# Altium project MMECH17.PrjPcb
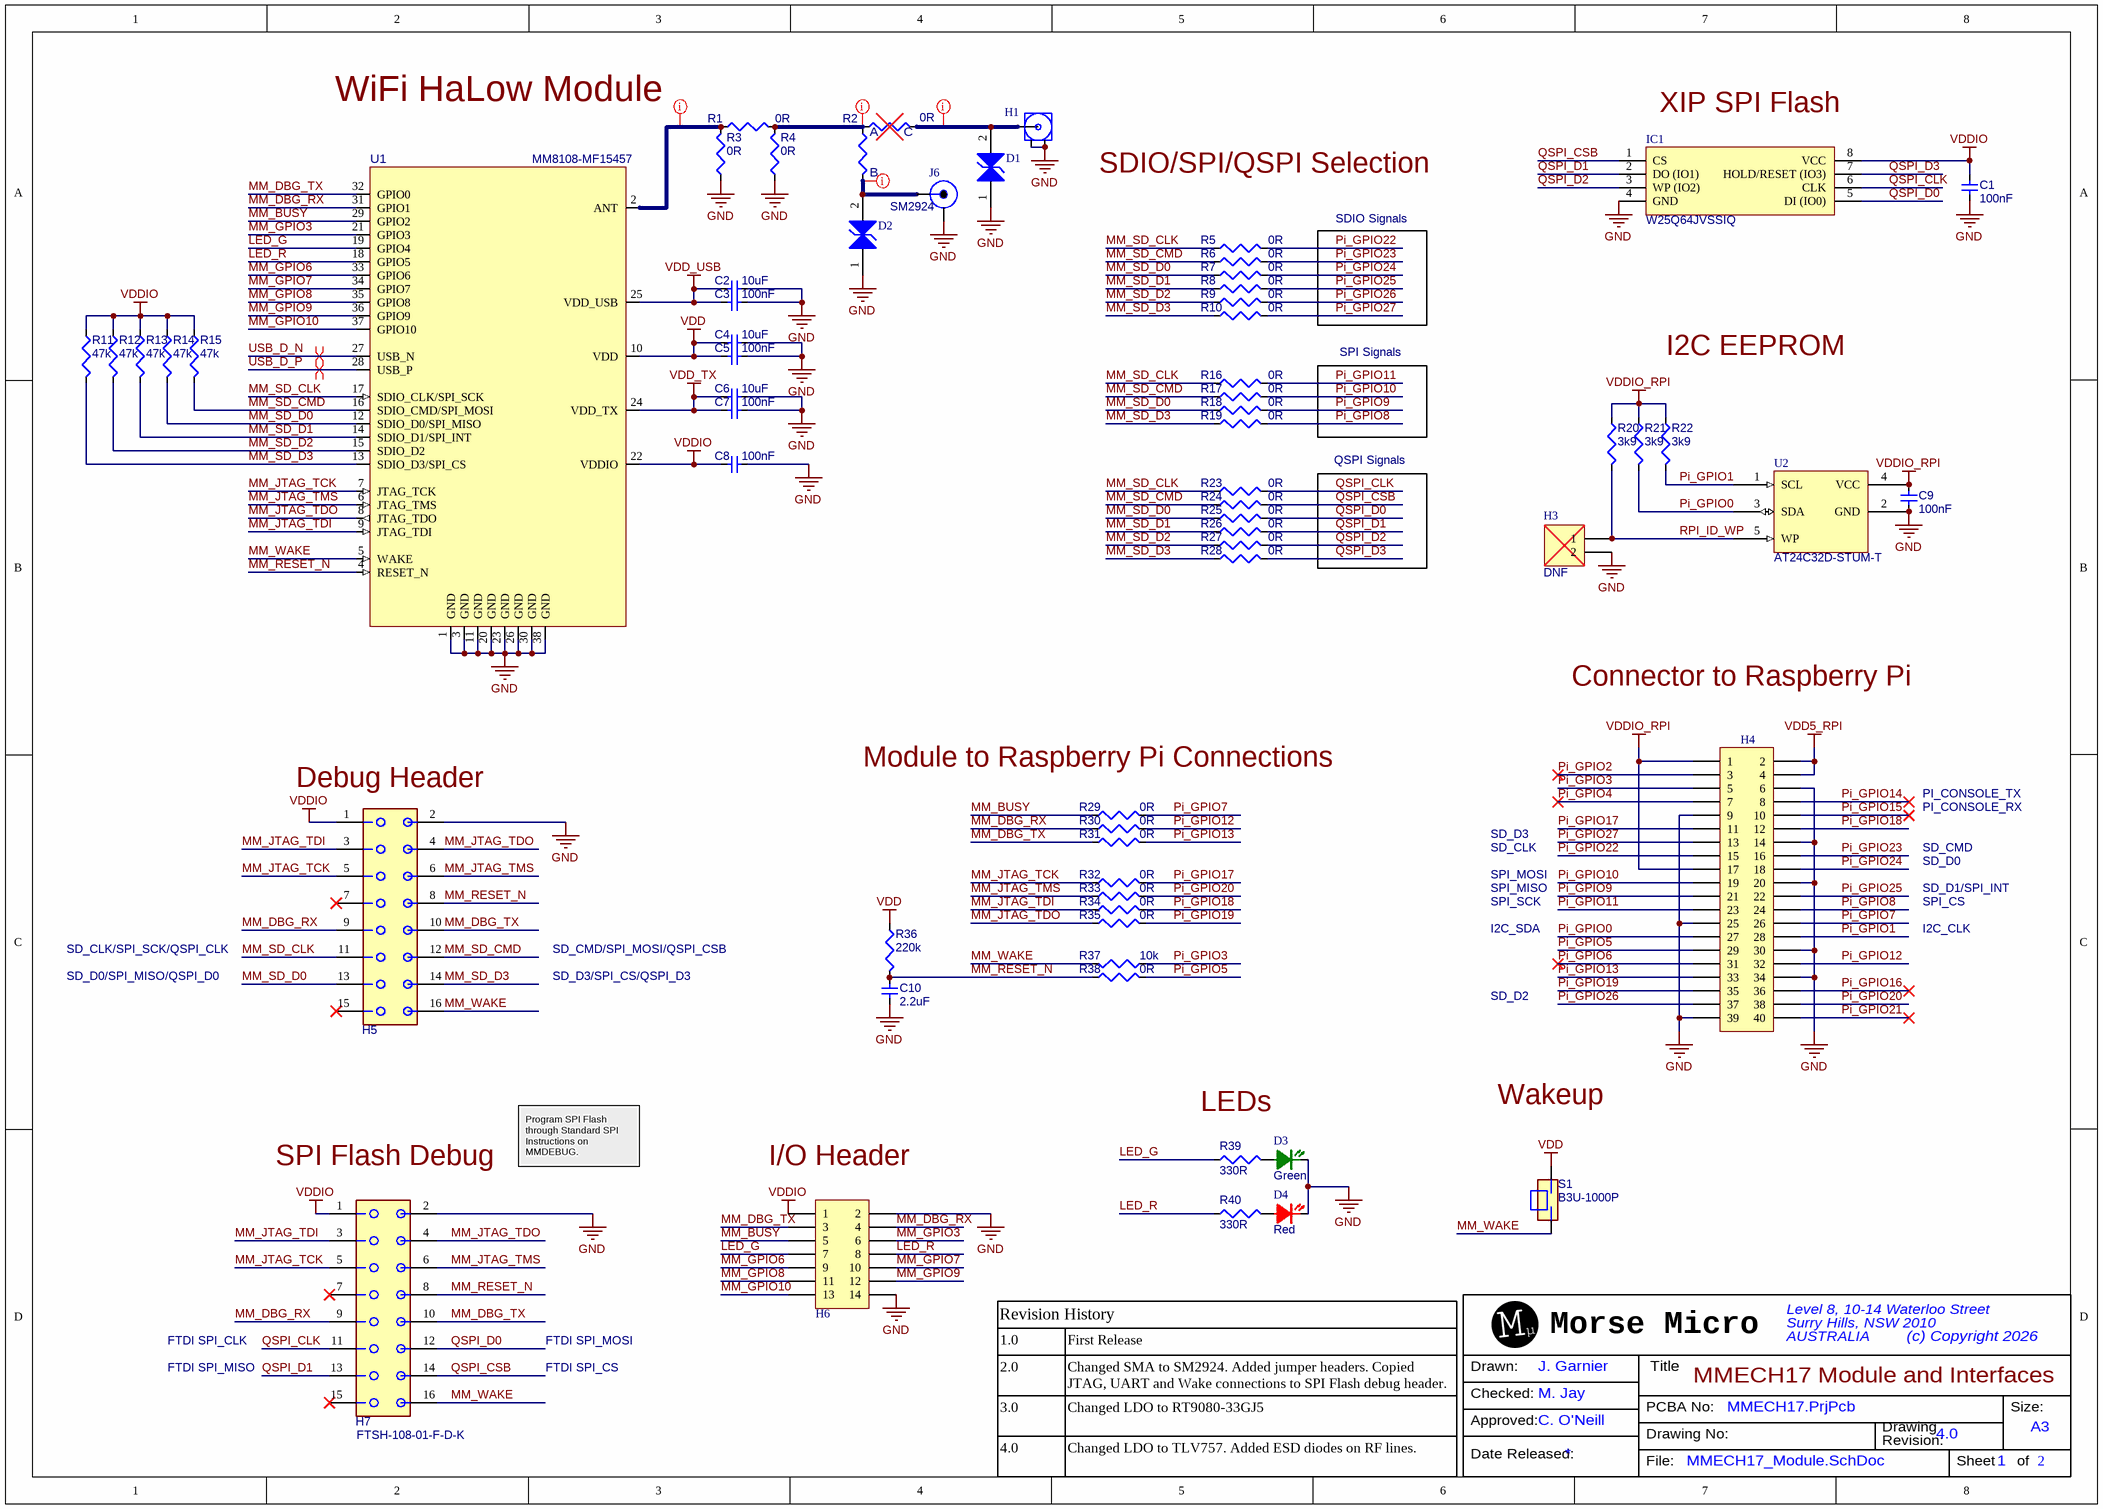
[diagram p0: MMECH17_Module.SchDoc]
ApprovedBy: C. O'Neill; CheckedBy: M. Jay; DrawnBy: J. Garnier; Project: MMECH17; Revision: 4.0
2 sheets, 96 parts. Net scope: global (net labels, ports and power ports of the same name join across sheets).
Board file: MMECH17.PcbDoc
Sheets:
  MMECH17_Module.SchDoc
  MMECH17_Power.SchDoc

## Sheet MMECH17_Module.SchDoc: MMECH17 Module and Interfaces
size A3; SheetNumber: 1; SheetTotal: 2; PageSetup: Record=PageOptions¦CenterHorizontal=True¦CenterVertical=True¦PrintScale=1.04¦XCorrection=1.00¦YCorrection=1.00¦PrintKind=0¦BorderSize=5000000¦LeftOffset=0¦BottomOffset=0¦Orientation=2¦PaperLength=1000¦PaperWidth=1000¦Scale=100¦PaperSource=7¦PrintQuality=-4¦MediaType=1¦DitherType=10¦PaperKind=A3¦PrintScaleMode=1

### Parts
C1  value 100nF  [0402_cap]  (hidden comment: C0402C104K8RACTU)
C2  value 10uF  [0603_cap]  (hidden comment: GRM188R61E106MA73J)
C3  value 100nF  [0402_cap]  (hidden comment: C0402C104K8RACTU)
C4  value 10uF  [0603_cap]  (hidden comment: GRM188R61E106MA73J)
C5  value 100nF  [0402_cap]  (hidden comment: C0402C104K8RACTU)
C6  value 10uF  [0603_cap]  (hidden comment: GRM188R61E106MA73J)
C7  value 100nF  [0402_cap]  (hidden comment: C0402C104K8RACTU)
C8  value 100nF  [0402_cap]  (hidden comment: C0402C104K8RACTU)
C9  value 100nF  [0402_cap]  (hidden comment: C0402C104K8RACTU)
C10  value 2.2uF  [0402_cap]  (hidden comment: JMK105BJ225MV-F)
D1  ESD103B102ELE6327XTMA1  [INF-TSLP-2-20_V]  (value not drawn)
D2  ESD103B102ELE6327XTMA1  [INF-TSLP-2-20_V]  (value not drawn)
D3  value Green  [LED_0402_GREEN]  (hidden comment: XZVGR68W-3)
D4  value Red  [LED_0402_RED]  (hidden comment: XZMDK68W-2)
H1  U.FL-R-SMT  [U_FL-R-SMT]  (value not drawn)
H3  DNF  [HDR1X2_DNF]  (no BOM)
H4  PPPC202LFBN-RC  [HDR2X20F]  (value not drawn)
H5  FTSH-108-01-F-D-K  [FTSH_108_D_K]  (value not drawn)
H6  PBC07DFAN  [HDR2X7]  (value not drawn)
H7  FTSH-108-01-F-D-K  [FTSH_108_D_K]
IC1  W25Q64JVSSIQ  [SOIC127P790X216-8N]
J6  SM2924  [SM2924]
R1  value 0R  [0603_res_rnd]  (hidden comment: RC0603JR-070RL)
R2  value 0R  [0603_res_ab_ra]  (hidden comment: RC0603JR-070RL)
R3  value 0R  [0603_res_rnd]  (hidden comment: RC0603JR-070RL)
R4  value 0R  [0603_res_rnd]  (hidden comment: RC0603JR-070RL)
R5  value 0R  [0603_res]  (hidden comment: ERJ-3GEY0R00V)
R6  value 0R  [0603_res]  (hidden comment: ERJ-3GEY0R00V)
R7  value 0R  [0603_res]  (hidden comment: ERJ-3GEY0R00V)
R8  value 0R  [0603_res]  (hidden comment: ERJ-3GEY0R00V)
R9  value 0R  [0603_res]  (hidden comment: ERJ-3GEY0R00V)
R10  value 0R  [0603_res]  (hidden comment: ERJ-3GEY0R00V)
R11  value 47k  [0402_res]  (hidden comment: MCR01MZPF4702)
R12  value 47k  [0402_res]  (hidden comment: MCR01MZPF4702)
R13  value 47k  [0402_res]  (hidden comment: MCR01MZPF4702)
R14  value 47k  [0402_res]  (hidden comment: MCR01MZPF4702)
R15  value 47k  [0402_res]  (hidden comment: MCR01MZPF4702)
R16  value 0R  [0603_res]  (hidden comment: ERJ-3GEY0R00V)
R17  value 0R  [0603_res]  (hidden comment: ERJ-3GEY0R00V)
R18  value 0R  [0603_res]  (hidden comment: ERJ-3GEY0R00V)
R19  value 0R  [0603_res]  (hidden comment: ERJ-3GEY0R00V)
R20  value 3k9  [0402_res]  (hidden comment: RC0402FR-073K9L)
R21  value 3k9  [0402_res]  (hidden comment: RC0402FR-073K9L)
R22  value 3k9  [0402_res]  (hidden comment: RC0402FR-073K9L)
R23  value 0R  [0603_res]  (hidden comment: ERJ-3GEY0R00V)
R24  value 0R  [0603_res]  (hidden comment: ERJ-3GEY0R00V)
R25  value 0R  [0603_res]  (hidden comment: ERJ-3GEY0R00V)
R26  value 0R  [0603_res]  (hidden comment: ERJ-3GEY0R00V)
R27  value 0R  [0603_res]  (hidden comment: ERJ-3GEY0R00V)
R28  value 0R  [0603_res]  (hidden comment: ERJ-3GEY0R00V)
R29  value 0R  [0603_res]  (hidden comment: ERJ-3GEY0R00V)
R30  value 0R  [0603_res]  (hidden comment: ERJ-3GEY0R00V)
R31  value 0R  [0603_res]  (hidden comment: ERJ-3GEY0R00V)
R32  value 0R  [0603_res]  (hidden comment: ERJ-3GEY0R00V)
R33  value 0R  [0603_res]  (hidden comment: ERJ-3GEY0R00V)
R34  value 0R  [0603_res]  (hidden comment: ERJ-3GEY0R00V)
R35  value 0R  [0603_res]  (hidden comment: ERJ-3GEY0R00V)
R36  value 220k  [0402_res]  (hidden comment: RC0402FR-07220KL)
R37  value 10k  [0603_res]  (hidden comment: RG1608P-103-B-T5)
R38  value 0R  [0603_res]  (hidden comment: ERJ-3GEY0R00V)
R39  value 330R  [0402_res]  (hidden comment: RC0402FR-07330RL)
R40  value 330R  [0402_res]  (hidden comment: RC0402FR-07330RL)
S1  B3U-1000P  [B3U-1000P]
U1  value MM8108-MF15457  [MF15]  (hidden comment: MM8108-MF15)
U2  AT24C32D-STUM-T  [SOT-23_5]

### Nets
GND: C1.1 C2.2 C3.2 C4.2 C5.1 C6.2 C7.2 C8.2 C9.1 C10.2 D1.1(C) D2.1(C) D3.K D4.K H1.2 H1.3 H3.2 H4.6 H4.9 H4.14 H4.20 H4.25 H4.30 H4.34 H4.39 H5.2 H6.2 H6.14 H7.2 IC1.4(GND) J6.2 R3.1 R4.1 U1.1(GND) U1.3(GND) U1.11(GND) U1.20(GND) U1.23(GND) U1.26(GND) U1.30(GND) U1.38(GND) U2.2(GND)
VDD: C4.1 C5.2 R36.1 S1.2 U1.10(VDD)
VDD5_RPI: H4.2 H4.4
VDD_TX: C6.1 C7.1 U1.24(VDD_TX)
VDD_USB: C2.1 C3.1 U1.25(VDD_USB)
VDDIO: C1.2 C8.1 H5.1 H6.1 H7.1 IC1.8(VCC) R11.1 R12.1 R13.1 R14.1 R15.1 U1.22(VDDIO)
VDDIO_RPI: C9.2 H4.1 H4.17 R20.1 R21.1 R22.1 U2.4(VCC)
LED_G: H6.7 R39.1 U1.19(GPIO4)
LED_R: H6.8 R40.1 U1.18(GPIO5)
MM_BUSY: H6.5 R29.1 U1.29(GPIO2)
MM_DBG_RX: H5.9 H6.4 H7.9 R30.1 U1.31(GPIO1)
MM_DBG_TX: H5.10 H6.3 H7.10 R31.1 U1.32(GPIO0)
MM_GPIO3: H6.6 U1.21(GPIO3)
MM_GPIO6: H6.9 U1.33(GPIO6)
MM_GPIO7: H6.10 U1.34(GPIO7)
MM_GPIO8: H6.11 U1.35(GPIO8)
MM_GPIO9: H6.12 U1.36(GPIO9)
MM_GPIO10: H6.13 U1.37(GPIO10)
MM_JTAG_TCK: H5.5 H7.5 R32.1 U1.7(JTAG_TCK)
MM_JTAG_TDI: H5.3 H7.3 R34.1 U1.9(JTAG_TDI)
MM_JTAG_TDO: H5.4 H7.4 R35.1 U1.8(JTAG_TDO)
MM_JTAG_TMS: H5.6 H7.6 R33.1 U1.6(JTAG_TMS)
MM_RESET_N: C10.1 H5.8 H7.8 R36.2 R38.1 U1.4(RESET_N)
MM_SD_CLK: H5.11 R5.1 R16.1 R23.1 U1.17(SDIO_CLK/SPI_SCK)
MM_SD_CMD: H5.12 R6.1 R15.2 R17.1 R24.1 U1.16(SDIO_CMD/SPI_MOSI)
MM_SD_D0: H5.13 R7.1 R14.2 R18.1 R25.1 U1.12(SDIO_D0/SPI_MISO)
MM_SD_D1: R8.1 R13.2 R26.1 U1.14(SDIO_D1/SPI_INT)
MM_SD_D2: R9.1 R12.2 R27.1 U1.15(SDIO_D2)
MM_SD_D3: H5.14 R10.1 R11.2 R19.1 R28.1 U1.13(SDIO_D3/SPI_CS)
MM_WAKE: H5.16 H7.16 R37.1 S1.1 U1.5(WAKE)
Pi_GPIO0: H4.27 R21.2 U2.3(SDA)
Pi_GPIO1: H4.28 R22.2 U2.1(SCL)
Pi_GPIO2: H4.3
Pi_GPIO3: H4.5 R37.2
Pi_GPIO4: H4.7
Pi_GPIO5: H4.29 R38.2
Pi_GPIO6: H4.31
Pi_GPIO7: H4.26 R29.2
Pi_GPIO8: H4.24 R19.2
Pi_GPIO9: H4.21 R18.2
Pi_GPIO10: H4.19 R17.2
Pi_GPIO11: H4.23 R16.2
Pi_GPIO12: H4.32 R30.2
Pi_GPIO13: H4.33 R31.2
Pi_GPIO14: H4.8
Pi_GPIO15: H4.10
Pi_GPIO16: H4.36
Pi_GPIO17: H4.11 R32.2
Pi_GPIO18: H4.12 R34.2
Pi_GPIO19: H4.35 R35.2
Pi_GPIO20: H4.38 R33.2
Pi_GPIO21: H4.40
Pi_GPIO22: H4.15 R5.2
Pi_GPIO23: H4.16 R6.2
Pi_GPIO24: H4.18 R7.2
Pi_GPIO25: H4.22 R8.2
Pi_GPIO26: H4.37 R9.2
Pi_GPIO27: H4.13 R10.2
QSPI_CLK: H7.11 IC1.6(CLK) R23.2
QSPI_CSB: H7.14 IC1.1(CS) R24.2
QSPI_D0: H7.12 IC1.5(DI_(IO0)) R25.2
QSPI_D1: H7.13 IC1.2(DO_(IO1)) R26.2
QSPI_D2: IC1.3(WP_(IO2)) R27.2
QSPI_D3: IC1.7(HOLD/RESET_(IO3)) R28.2
RPI_ID_WP: H3.1 R20.2 U2.5(WP)
USB_D_N: U1.27(USB_N)
USB_D_P: U1.28(USB_P)
NetD1_2: D1.2(C) H1.1 R2.C
NetD2_2: D2.2(C) J6.1 R2.B
NetD3_A: D3.A R39.2
NetD4_A: D4.A R40.2
NetR1_1: R1.1 R3.2 U1.2(ANT)
NetR1_2: R1.2 R2.A R4.2

Not connected (* = marked no-connect by the designer): H5 7* 15*; H7 7* 15*

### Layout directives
net class RF-Net: NetD1_2, NetD2_2, NetR1_1, NetR1_2
differential pair; differential pair class DIFF_90: USB_D_N, USB_D_P

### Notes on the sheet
- WiFi HaLow Module
- SDIO/SPI/QSPI Selection
- (near IC1) XIP SPI Flash
- SDIO Signals
- SPI Signals
- I2C EEPROM
- QSPI Signals
- Connector to Raspberry Pi
- Module to Raspberry Pi Connections
- (near H5) Debug Header
- SD_CLK
- SD_D3
- SD_CMD
- PI_CONSOLE_TX
- PI_CONSOLE_RX
- SPI_SCK
- SPI_MISO
- SPI_MOSI
- SD_D0
- SD_D1/SPI_INT
- SPI_CS
- SD_D0/SPI_MISO/QSPI_D0
- SD_CLK/SPI_SCK/QSPI_CLK
- SD_CMD/SPI_MOSI/QSPI_CSB
- SD_D3/SPI_CS/QSPI_D3
- I2C_SDA
- I2C_CLK
- SD_D2
- LEDs
- Wakeup
- (near H7) SPI Flash Debug
- Program SPI Flash through Standard SPI Instructions on MMDEBUG.
- (near H6) I/O Header
- Revision History
- FTDI SPI_CLK
- FTDI SPI_MISO
- FTDI SPI_CS
- FTDI SPI_MOSI
- 1.0
- 2.0
- First Release
- Changed SMA to SM2924. Added jumper headers. Copied JTAG, UART and Wake connections to SPI Flash debug header.
- 3.0
- Changed LDO to RT9080-33GJ5
- 4.0
- Changed LDO to TLV757. Added ESD diodes on RF lines.

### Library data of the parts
C1 C3 C7 C9 = CAP0025-15: CAP CER 100NF 10V ±10% X7R 0402; Subtype: Ceramic; Generic Allowed: Yes
C2 C4 C6 = CAP0197-10: CAP CER 10UF 25V ±20% X5R 0603; Generic Allowed: Yes; Subtype: Ceramic
C5 C8 = CAP0025-15: CAP CER 100NF 10V ±10% X7R 0402; Generic Allowed: Yes; Subtype: Ceramic
C10 = CAP0027-15: CAP CER 2.2UF 6.3V ±20% X5R 0402; Generic Allowed: Yes; Subtype: Ceramic
D1 D2 = DIO0089-8: ESD103B102 Series 1 Line 15 V 0.2pF Bi-Direction TVS Protection Device-TSLP-2-20
D3 = DIO0053-7: LED GREEN 0402 SMD; Generic Allowed: Yes; Voltage: 2.0V
D4 = DIO0052-9: LED RED 0402 SMD; Generic Allowed: Yes; Voltage: 1.95V
H1 = JCK0091-7: U.FL RF Connector; Generic Allowed: Yes
H3 = HDR0067-2: Conn Straight Header 2x1 0.100" 2 POS (DNF)
H4 = HDR0101-2: Conn Female Header 20x2 0.100" 40 POS; Generic Allowed: Yes
H5 H7 = HDR0110-2: Board Connector, 16 Contact(s), 2 Row(s), Male, Straight, 0.05 inch Pitch, Solder Terminal, Locking
H6 = HDR0095-2: Conn Straight Header 7x2 0.100" 14 POS; Generic Allowed: Yes
IC1 = ICT0225-3: Integrated Circuit; Manufacturer_Name: Winbond
J6 = JCK0138-23: Wanshih RF SMD SMA connector with 2 GND pillars - Smaller Connector Barrel
R1 R3 R4 = RES0119-8: RES SMD 0R OHM ±5% 1/10W 0603; Generic Allowed: Yes
R2 = RES0284-2: RES 0 OHM JUMPER 1/10W 0603; Subtype: Thick Film; Generic Allowed: Yes
R5-R10 R16-R19 R23-R35 R38 = RES0003-8: RES SMD 0R OHM ±1% 1/10W 0603; Generic Allowed: Yes
R11-R15 = RES0086-13: RES SMD 47K OHM ±1% 1/16W 0402; Generic Allowed: Yes
R20-R22 = RES0204-13: RES SMD 3K9 OHM ±1% 1/16W 0402; Generic Allowed: Yes
R36 = RES0064-13: RES SMD 220K OHM ±1% 1/16W 0402; Generic Allowed: Yes
R37 = RES0143-8: RES SMD 10K OHM ±0.1% 1/10W 0603; Generic Allowed: Yes
R39 R40 = RES0025-14: RES SMD 330R OHM ±1% 1/16W 0402; Generic Allowed: Yes
S1 = SWH0022-1: SWITCH TACTILE SPST-NO 0.05A 12V
U1 = MOD0024-12: Generic Allowed: No
U2 = ICT0037-3: IC EEPROM 32KBIT I2C SOT23-5; Generic Allowed: No

## Sheet MMECH17_Power.SchDoc: MMECH17 Power
size A3; CompanyName: Morse Micro; SheetNumber: 2; SheetTotal: 2; pageName: Regulators; PageSetup: Record=PageOptions¦CenterHorizontal=True¦CenterVertical=True¦PrintScale=1.04¦XCorrection=1.00¦YCorrection=1.00¦PrintKind=0¦BorderSize=5000000¦LeftOffset=0¦BottomOffset=0¦Orientation=2¦PaperLength=1000¦PaperWidth=1000¦Scale=100¦PaperSource=7¦PrintQuality=-4¦MediaType=1¦DitherType=10¦PaperKind=A3¦PrintScaleMode=1
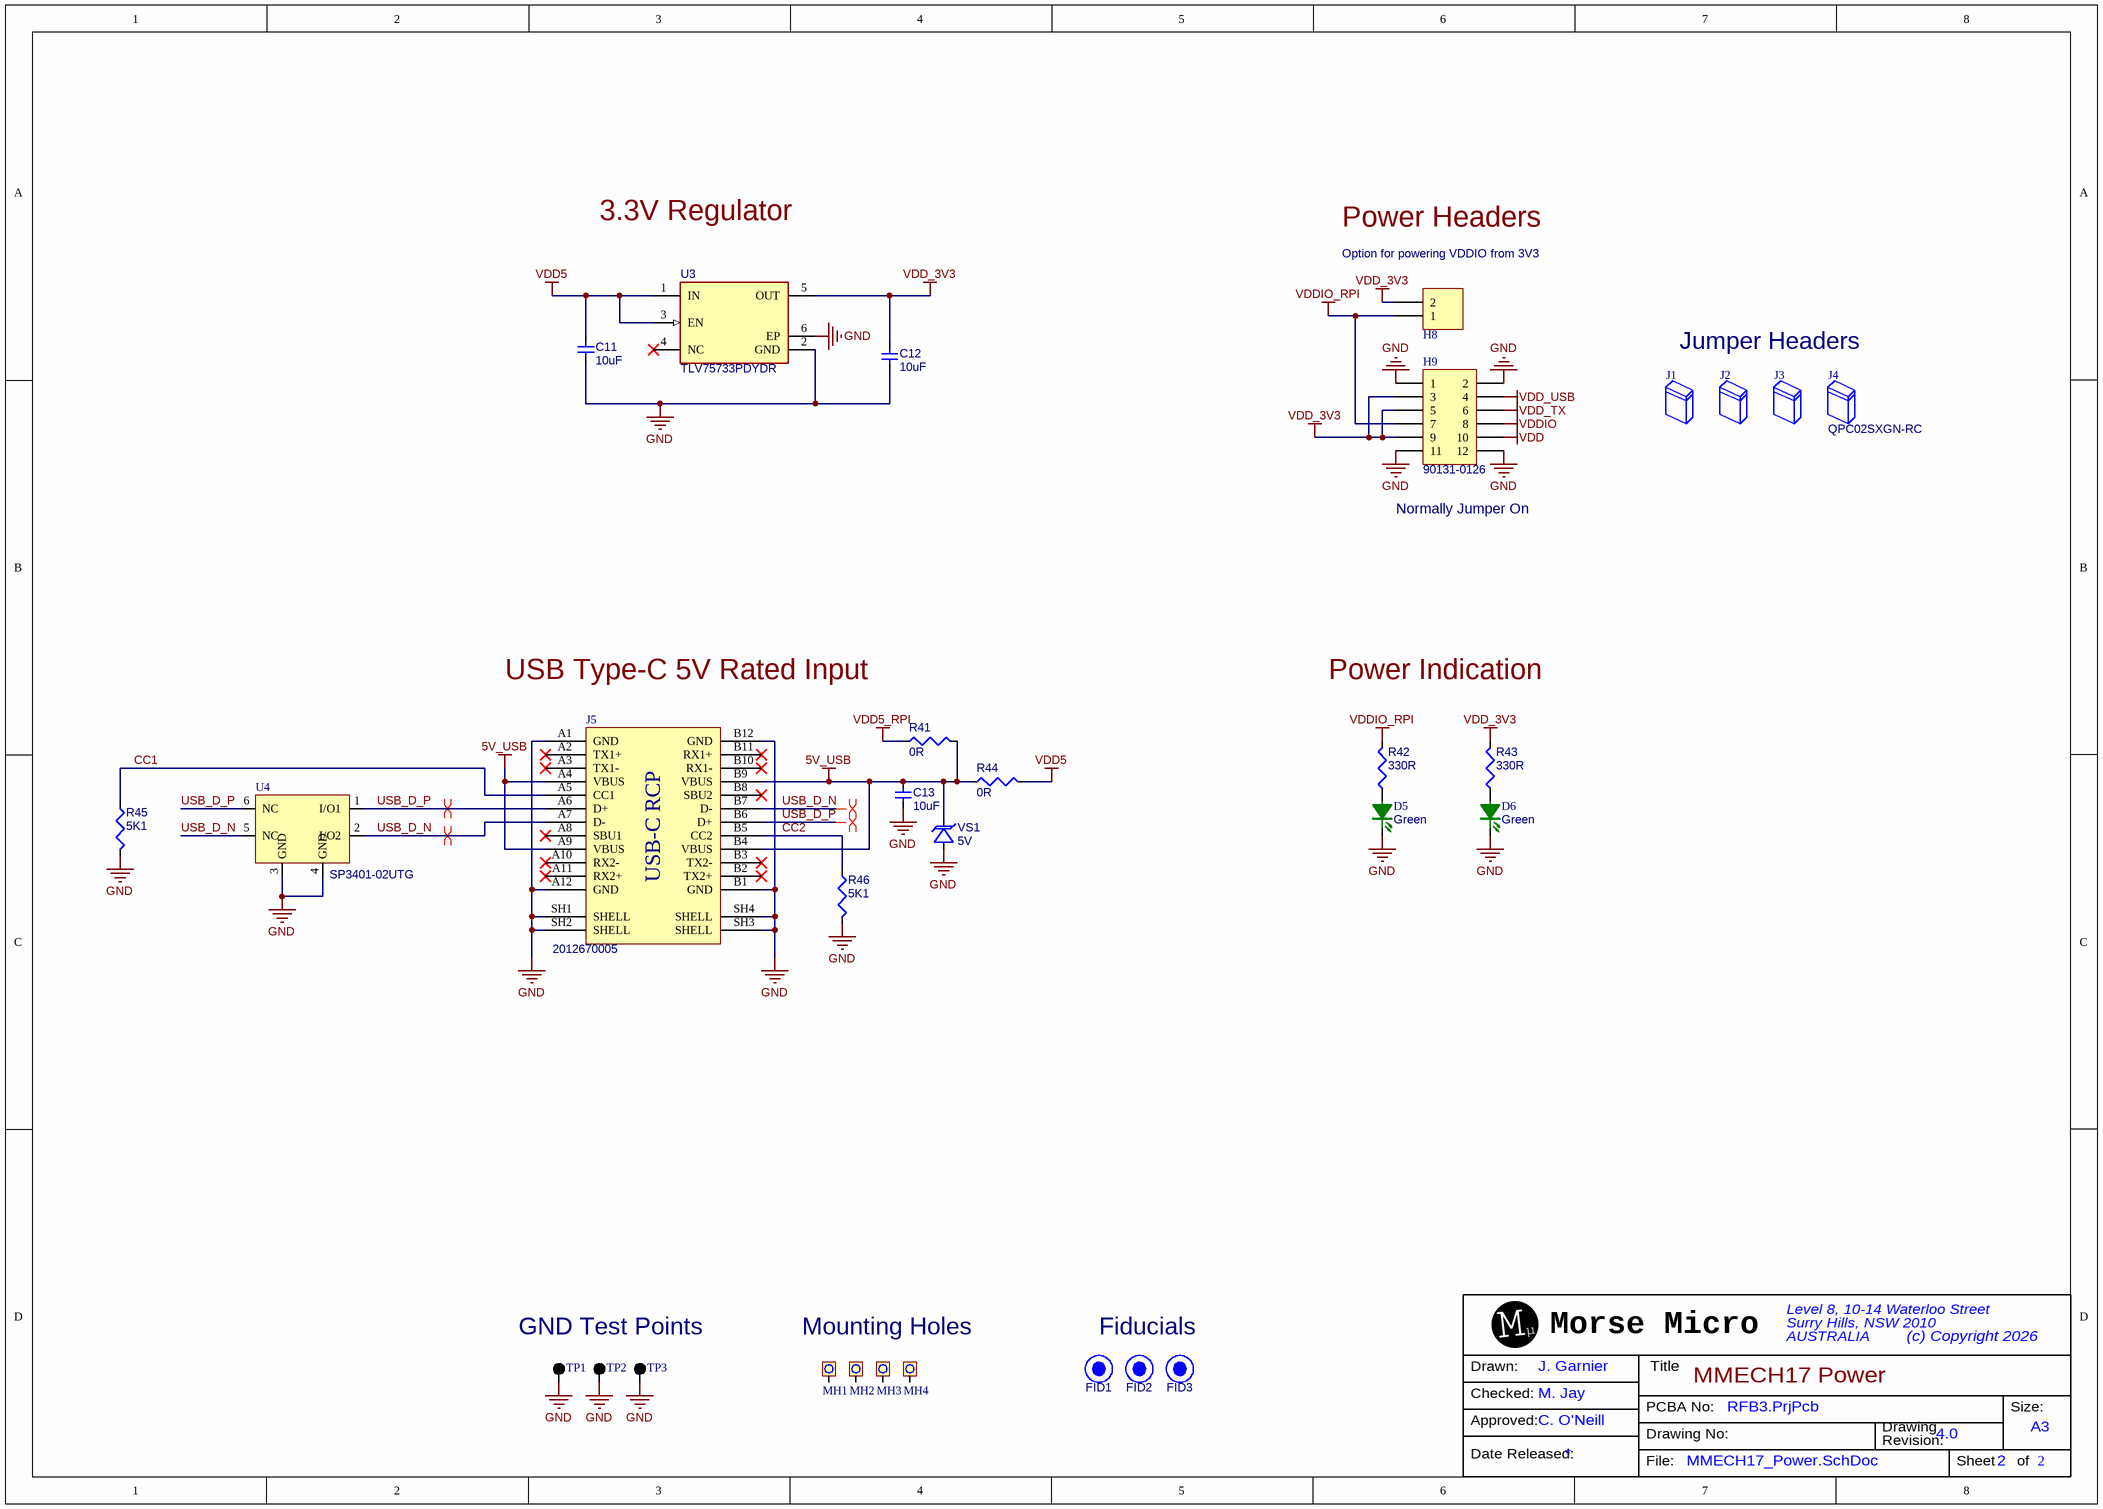
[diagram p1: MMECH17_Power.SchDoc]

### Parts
C11  value 10uF  [0402_cap_rnd]  (hidden comment: CL05A106MP8NUB8)
C12  value 10uF  [0402_cap_rnd]  (hidden comment: CL05A106MP8NUB8)
C13  value 10uF  [0603_cap]  (hidden comment: GRM188R61E106MA73J)
D5  value Green  [LED_0402_GREEN]  (hidden comment: XZVGR68W-3)
D6  value Green  [LED_0402_GREEN]  (hidden comment: XZVGR68W-3)
FID1  1mm Round Fiducial, 0.5mm Space  [FIDUCIAL_1MM]  (value not drawn)  (no BOM)
FID2  1mm Round Fiducial, 0.5mm Space  [FIDUCIAL_1MM]  (value not drawn)  (no BOM)
FID3  1mm Round Fiducial, 0.5mm Space  [FIDUCIAL_1MM]  (value not drawn)  (no BOM)
H8  2011-1X02G00SB-1  [HDR1X2]  (value not drawn)
H9  90131-0126  [HDR2X6]
J1  QPC02SXGN-RC  [FP-QPC02SXGN-RC-MFG]  (value not drawn)
J2  QPC02SXGN-RC  [FP-QPC02SXGN-RC-MFG]  (value not drawn)
J3  QPC02SXGN-RC  [FP-QPC02SXGN-RC-MFG]  (value not drawn)
J4  QPC02SXGN-RC  [FP-QPC02SXGN-RC-MFG]
J5  2012670005  [USB-C_RCP]
MH1  PAD0009  [MH_300_275_NPTH]  (value not drawn)
MH2  PAD0009  [MH_300_275_NPTH]  (value not drawn)
MH3  PAD0009  [MH_300_275_NPTH]  (value not drawn)
MH4  PAD0009  [MH_300_275_NPTH]  (value not drawn)
R41  value 0R  [0603_res_rnd]  (hidden comment: RC0603JR-070RL)
R42  value 330R  [0402_res]  (hidden comment: MCR01MZPF3300)
R43  value 330R  [0402_res]  (hidden comment: MCR01MZPF3300)
R44  value 0R  [0603_res_rnd]  (hidden comment: RC0603JR-070RL)
R45  value 5K1  [0402_res]  (hidden comment: RC0402FR-075K1L)
R46  value 5K1  [0402_res]  (hidden comment: RC0402FR-075K1L)
TP1  TP-BLK  [FP-5001-MFG]  (value not drawn)
TP2  TP-BLK  [FP-5001-MFG]  (value not drawn)
TP3  TP-BLK  [FP-5001-MFG]  (value not drawn)
U3  TLV75733PDYDR  [TLV75533PDYDR]
U4  SP3401-02UTG  [SP3401-02UTG-Footprint-1]
VS1  value 5V  [SOD-523]  (hidden comment: ESD5Z5.0T1G)

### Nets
5V_USB: C13.1 J5.A4(VBUS) J5.A9(VBUS) J5.B4(VBUS) J5.B9(VBUS) R41.2 R44.1 VS1.K
GND: C11.2 C12.2 C13.2 D5.K D6.K H9.1 H9.2 H9.11 H9.12 J5.A1(GND) J5.A12(GND) J5.B1(GND) J5.B12(GND) J5.SH1(SHELL) J5.SH2(SHELL) J5.SH3(SHELL) J5.SH4(SHELL) R45.2 R46.2 TP1.1 TP2.1 TP3.1 U3.2(GND) U3.6(EP) U4.3(GND) U4.4(GND) VS1.A
VDD: H9.10
VDD5: C11.1 R44.2 U3.1(IN) U3.3(EN)
VDD5_RPI: R41.1
VDD_3V3: C12.1 H8.2 H9.3 H9.5 H9.9 R43.2 U3.5(OUT)
VDD_TX: H9.6
VDD_USB: H9.4
VDDIO: H9.8
VDDIO_RPI: H8.1 H9.7 R42.2
CC1: J5.A5(CC1) R45.1
CC2: J5.B5(CC2) R46.1
USB_D_N: J5.A7(D-) J5.B7(D-) U4.2(I/O2) U4.5(NC)
USB_D_P: J5.A6(D+) J5.B6(D+) U4.1(I/O1) U4.6(NC)
NetD5_A: D5.A R42.1
NetD6_A: D6.A R43.1

Not connected (* = marked no-connect by the designer): J5 A2(TX1+)* A3(TX1-)* A8(SBU1)* A10(RX2-)* A11(RX2+)* B2(TX2+)* B3(TX2-)* B8(SBU2)* B10(RX1-)* B11(RX1+)*; MH1 1; MH2 1; MH3 1; MH4 1; U3 4(NC)*

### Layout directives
differential pair: USB_D_N, USB_D_P

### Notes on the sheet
- 3.3V Regulator
- Power Headers
- (near H8) Option for powering VDDIO from 3V3
- Jumper Headers
- (near H9) Normally Jumper On
- USB Type-C 5V Rated Input
- Power Indication
- GND Test Points
- Mounting Holes
- Fiducials

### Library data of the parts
C11 C12 = CAP0046-16: CAP CER 10UF 10V 20% X5R 0402; Generic Allowed: Yes; Subtype: Ceramic
C13 = CAP0197-10: as C2 on sheet MMECH17_Module
D5 D6 = DIO0053-7: as D3 on sheet MMECH17_Module
FID1-FID3 = FID00000-1
H8 = HDR0006-4: Conn Straight Header 2x1 0.100" 2 POS; Generic Allowed: Yes
H9 = HDR0014-2: Conn Straight Header 6x2 0.100" 12 POS; Generic Allowed: Yes
J1-J4 = CMP-00006-7: Shunts/Jumper Connector; Manufacturer Series: QPC; Rated Current (Signal): 3A; Contact Pattern: RECTANGULAR; Body Depth: 0.235inch; Mating Contact Pitch: 0.1inch; Contact Style: SQ PIN-SKT; Body Breadth: 0.097inch; Polarization Key: POLARIZED HOUSING; Number of Contacts: 1; Body Length: 0.197inch; Reliability: COMMERCIAL; Mounting Option 1: LOCKING; Reference Standard: UL
J5 = JCK0027-1: CONN RCP USB3.1 TYPEC 24P SMD RA; Generic Allowed: Yes
MH1-MH4 = PAD0009-2: MH NPTH 3.00mm DIA 2.75mm HOLE; Shape: Round
R41 R44 = RES0119-8: as R1 on sheet MMECH17_Module
R42 R43 = RES0073-13: RES SMD 330R OHM ±1% 1/16W 0402; Generic Allowed: Yes
R45 R46 = RES0027-13: RES SMD 5K1 OHM ±1% 1/16W 0402; Generic Allowed: Yes
TP1-TP3 = TPN0006-3: Test Point PCB, Black 0.040"D; Value: Black Color; Generic Allowed: Yes
U3 = ICT0296-2: 1-A, low-IQ high-accuracy low-dropout (LDO) voltage regulator with enable 5-SOT-23 -40 to 125; Manufacturer Lifecycle Status: ACTIVE
U4 = CMP-00020-9: 9V Clamp 10A (8/20µs) Ipp Tvs Diode Surface Mount 6-µDFN (1.6x1); Voltage: 6.5V (Breakdown); Generic Allowed: No
VS1 = DIO0073-2: TVS Diode,5V@9.4Amp, SOD-523 SMD; Current: 9.4A

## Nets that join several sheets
GND: MMECH17_Module (42 pins), MMECH17_Power (27 pins)
VDD: MMECH17_Module (5 pins), MMECH17_Power (H9.10)
VDD5_RPI: MMECH17_Module (H4.2 H4.4), MMECH17_Power (R41.1)
VDD_TX: MMECH17_Module (C6.1 C7.1 U1.24), MMECH17_Power (H9.6)
VDD_USB: MMECH17_Module (C2.1 C3.1 U1.25), MMECH17_Power (H9.4)
VDDIO: MMECH17_Module (12 pins), MMECH17_Power (H9.8)
VDDIO_RPI: MMECH17_Module (7 pins), MMECH17_Power (H8.1 H9.7 R42.2)
USB_D_N: MMECH17_Module (U1.27), MMECH17_Power (J5.A7 J5.B7 U4.2 U4.5)
USB_D_P: MMECH17_Module (U1.28), MMECH17_Power (J5.A6 J5.B6 U4.1 U4.6)

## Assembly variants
Default Build: not fitted C1 H3 H7 IC1 R3 R4 R16 R17 R18 R19 R23 R24 R25 R26 R27 R28
Full Network Offload: not fitted C9 D1 H1 H3 R3 R4 R5 R6 R7 R8 R9 R10 R16 R17 R18 R19 R20 R21 R22 U2
Kit Build (U.FL): not fitted C1 D2 H3 H6 H7 IC1 J5 J6 R3 R4 R16 R17 R18 R19 R23 R24 R25 R26 R27 R28 R45 S1 TP1 TP2 TP3 U4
